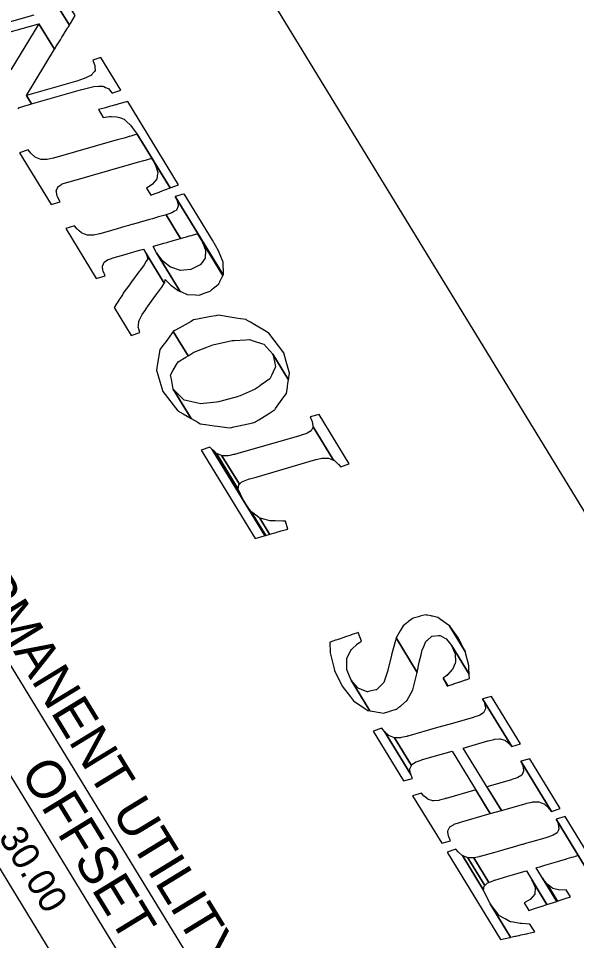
# Model space of a CAD drawing. Extents: x 1753086 to 1770987, y 792577 to 812636.
# Drawn here: x 1766380 to 1767286, y 803112 to 804610 of the extents above; entities that cross this region are included whole.
import ezdxf

# ---------------------------------------------------------------- set-up
doc = ezdxf.new("R2010")
doc.units = 0
for name, color, linetype in [('CTL Sheet Border CELL', 7, 'Continuous'), ('CTL Sheet Notes CELL', 7, 'Continuous'), ('CTL Sheet Table Cell', 7, 'Continuous'), ('CTL Sheet Text', 7, 'Continuous'), ('Sheet Data Field CELL', 7, 'Continuous')]:
    doc.layers.add(name, color=color, linetype=linetype)

msp = doc.modelspace()

# ---------------------------------------------------------------- linework, layer by layer
at = {"layer": 'CTL Sheet Border CELL'}
msp.add_lwpolyline([(1770671.7, 798289.4), (1762511, 811645.8), (1753161.6, 805933.4), (1761322.3, 792577)], close=True, dxfattribs=at)
at = {"layer": 'CTL Sheet Table Cell'}
for p, q in [((1765751, 804567), (1767551.4, 801620.3)), ((1765671.2, 804518.2), (1767471.6, 801571.5)), ((1765591.4, 804469.4), (1767391.8, 801522.7))]:
    msp.add_line(p, q, dxfattribs=at)
at = {"layer": 'Sheet Data Field CELL'}
for points in [[(1766432.4, 804650.2), (1766433.4, 804647.6), (1766462.8, 804599.6), (1766463.1, 804600.1), (1766463.4, 804600.6), (1766463.7, 804601.1), (1766463.7, 804601.2), (1766464.4, 804602.3), (1766472.2, 804615.1), (1766444.4, 804660.6), (1766431.4, 804656.4), (1766430.2, 804656), (1766430.4, 804655.7), (1766431.3, 804653.1)], [(1766472.7, 804507.8), (1766393.1, 804484.9), (1766401.4, 804471.3), (1766480.9, 804494.3), (1766483.2, 804494.9), (1766495.8, 804498), (1766500.2, 804499.1), (1766502.5, 804499.7), (1766509.9, 804500), (1766510.1, 804500), (1766517.3, 804500.3), (1766518.8, 804499.6), (1766521.4, 804498.3), (1766526, 804496.2), (1766526.8, 804495.8), (1766529.7, 804492.2), (1766529.6, 804492.2), (1766532.2, 804489), (1766532.2, 804489.1), (1766533.4, 804489.4), (1766533.4, 804489.5), (1766546.5, 804493.5), (1766513.8, 804547.1), (1766501.1, 804542.4), (1766503.1, 804536.8), (1766503.2, 804536.5), (1766504, 804534.1), (1766504.1, 804532.9), (1766504.2, 804531.8), (1766504.7, 804525.6), (1766503.6, 804524.3), (1766503.1, 804523.6), (1766498.8, 804518.4), (1766498.8, 804518.3), (1766492.9, 804515.4), (1766490.8, 804514.4), (1766487, 804512.6), (1766475, 804508.4)], [(1766519.3, 804464.7), (1766510.1, 804462.1), (1766517.8, 804449.4), (1766527.9, 804450.7), (1766530.5, 804450.7), (1766540.1, 804450.4), (1766544.1, 804449.1), (1766544.1, 804449.1), (1766551.9, 804446.4), (1766555.2, 804443.4), (1766562.3, 804436.8), (1766565, 804433.1), (1766573.1, 804422.1), (1766626.4, 804334.9), (1766640.2, 804340.1), (1766557.6, 804475.3), (1766543, 804471.3), (1766541.9, 804470.9), (1766541.5, 804470.8), (1766538.9, 804470.1), (1766537.7, 804469.7), (1766532.3, 804468.3), (1766529.6, 804467.5), (1766521.6, 804465.3)], [(1766396, 804396.6), (1766381.8, 804391.8), (1766433, 804308.1), (1766447.6, 804312.2), (1766443.5, 804320.6), (1766443, 804321.7), (1766441.8, 804328.6), (1766441.5, 804330.3), (1766443.9, 804336.2), (1766444, 804336.6), (1766450.7, 804340.9), (1766451.3, 804341.3), (1766460.4, 804344.4), (1766460.9, 804344.5), (1766564, 804373.9), (1766573.2, 804376.5), (1766575.4, 804377.1), (1766583.5, 804379.4), (1766586.2, 804380.2), (1766591.5, 804381.7), (1766592.7, 804382), (1766595.3, 804382.8), (1766595.7, 804382.9), (1766596.8, 804383.2), (1766626.3, 804334.8), (1766626.4, 804334.8), (1766573.1, 804422.1), (1766573, 804422.1), (1766571.9, 804421.8), (1766571.5, 804421.7), (1766568.9, 804420.9), (1766567.7, 804420.6), (1766562.4, 804419.1), (1766559.7, 804418.3), (1766551.7, 804416), (1766549.4, 804415.4), (1766540.2, 804412.8), (1766437.1, 804383.5), (1766436.6, 804383.4), (1766426.9, 804381.2), (1766426.1, 804381), (1766416.8, 804381.2), (1766416.4, 804381.2), (1766408.4, 804384.4), (1766407.5, 804384.8), (1766400.7, 804390.8), (1766400.4, 804391.1)], [(1766595.7, 804339.6), (1766587.9, 804334.7), (1766595.1, 804323), (1766603.9, 804326.3), (1766606, 804327.1), (1766613.6, 804330), (1766616.2, 804331), (1766616.2, 804331), (1766621.3, 804332.9), (1766622.4, 804333.3), (1766622.4, 804333.4), (1766624.9, 804334.3), (1766625.3, 804334.4), (1766626.3, 804334.8), (1766596.8, 804383.2), (1766602.6, 804371.6), (1766603, 804370.1), (1766606.3, 804359.8), (1766606, 804357.9), (1766604.9, 804349.5), (1766603.1, 804347.3), (1766597.6, 804340.8)], [(1766624.8, 804292.9), (1766619.9, 804291.2), (1766643.4, 804252.7), (1766648.4, 804254.1), (1766653, 804255.4), (1766658.1, 804256.9), (1766658.1, 804256.9), (1766660.9, 804257.7), (1766661.3, 804257.8), (1766667.4, 804259.5), (1766668, 804259.7), (1766670.6, 804260.5), (1766670.6, 804260.5), (1766671, 804260.6), (1766712.3, 804192.9), (1766712.7, 804193.7), (1766634.8, 804321.1), (1766636.9, 804316.3), (1766637.8, 804314.2), (1766638, 804313.7), (1766639.2, 804307), (1766639.5, 804305.1), (1766636.5, 804298.5), (1766636.1, 804298.3), (1766633.6, 804296.9), (1766629.2, 804294.3)], [(1766635.2, 804321.2), (1766634.8, 804321.1), (1766712.7, 804193.7), (1766712.9, 804194), (1766712.6, 804214.4), (1766704.9, 804232.9), (1766695.1, 804250.2), (1766649.4, 804325.1), (1766648.7, 804324.9), (1766645.6, 804324.1)], [(1766471.2, 804273.5), (1766457, 804268.7), (1766506.5, 804187.8), (1766521.1, 804191.8), (1766518.2, 804198.3), (1766517.9, 804199.2), (1766517.3, 804202.2), (1766516.7, 804206.1), (1766516.4, 804207.8), (1766518.1, 804211.6), (1766518.9, 804213.3), (1766519.4, 804214.4), (1766523, 804216.8), (1766525.6, 804218.3), (1766526.2, 804218.7), (1766526.3, 804218.8), (1766535.3, 804221.9), (1766535.7, 804222), (1766541.6, 804223.7), (1766554.8, 804227.5), (1766554.8, 804227.5), (1766563.7, 804230), (1766571, 804232.1), (1766576.6, 804233.7), (1766580.9, 804234.9), (1766583, 804235.5), (1766616.9, 804179.9), (1766617.6, 804180.9), (1766618.6, 804186.2), (1766627.7, 804176.7), (1766639.4, 804168.3), (1766642.9, 804166.7), (1766604.5, 804229.6), (1766598.8, 804239.9), (1766599.5, 804240.2), (1766605.3, 804241.8), (1766605.4, 804241.8), (1766616.3, 804245), (1766621.2, 804246.4), (1766631.1, 804249.2), (1766639.7, 804251.7), (1766643.4, 804252.7), (1766619.9, 804291.2), (1766616.2, 804290.1), (1766607.6, 804287.7), (1766597.7, 804284.8), (1766592.8, 804283.4), (1766581.9, 804280.3), (1766581.8, 804280.3), (1766576, 804278.6), (1766575.3, 804278.4), (1766574.7, 804278.3), (1766572.5, 804277.7), (1766566.9, 804276), (1766564.2, 804275.2), (1766560.6, 804274.2), (1766559.5, 804273.9), (1766557.4, 804273.3), (1766553.1, 804272.1), (1766547.6, 804270.5), (1766540.3, 804268.4), (1766531.4, 804265.9), (1766518.1, 804262.1), (1766512.3, 804260.4), (1766511.8, 804260.3), (1766502.3, 804258.2), (1766502.1, 804258.1), (1766501.4, 804258), (1766497.8, 804258), (1766492.8, 804258), (1766491.6, 804258.1), (1766489.1, 804259.1), (1766483.7, 804261.3), (1766482.7, 804261.7), (1766478.9, 804265.1), (1766476, 804267.7), (1766475.6, 804268)], [(1766671, 804260.6), (1766678.9, 804247), (1766712.1, 804192.6), (1766712.3, 804192.9)], [(1766608.4, 804224.2), (1766604.5, 804229.6), (1766642.9, 804166.7), (1766643.7, 804166.3), (1766645, 804165.8), (1766645, 804165.8), (1766654.2, 804161.7), (1766654.4, 804161.7), (1766667.6, 804161), (1766673.6, 804160.7), (1766683.1, 804164.2), (1766691.3, 804167.3), (1766694.2, 804169.7), (1766694.2, 804169.7), (1766698.1, 804172.9), (1766701.6, 804175.9), (1766705.6, 804179.1), (1766707, 804182.1), (1766707.3, 804182.6), (1766707.2, 804182.6), (1766710.4, 804189.1), (1766710.8, 804189.8), (1766712.1, 804192.5), (1766712.1, 804192.6), (1766678.9, 804247), (1766679, 804246.7), (1766684.1, 804233.5), (1766684, 804232.3), (1766683.4, 804221.6), (1766683.4, 804220.8), (1766681.6, 804218.4), (1766678.3, 804213.9), (1766675.4, 804209.9), (1766670.9, 804207.7), (1766667.6, 804206.1), (1766659.9, 804202.2), (1766648.7, 804201.4), (1766643.2, 804200.9), (1766627.3, 804206), (1766627, 804206.2), (1766614.4, 804215.9)], [(1766544.2, 804154), (1766535.5, 804140.3), (1766563.3, 804094.9), (1766577.1, 804100.1), (1766576, 804103.7), (1766575.9, 804104.2), (1766574.6, 804108.5), (1766574.8, 804110.9), (1766574.9, 804112), (1766575.5, 804117.7), (1766576.3, 804119.4), (1766576.8, 804120.5), (1766576.8, 804120.5), (1766579.1, 804125.1), (1766580.6, 804128.2), (1766580.6, 804128.2), (1766581, 804129), (1766581.1, 804129.1), (1766586.8, 804137.5), (1766587.1, 804138), (1766590.7, 804143.3), (1766599.1, 804154.9), (1766604.8, 804162.8), (1766609.6, 804169.1), (1766613.2, 804173.8), (1766615.7, 804177.9), (1766616.9, 804179.9), (1766587.5, 804228.1), (1766590, 804219.9), (1766587.6, 804215.6), (1766584.5, 804210), (1766579.8, 804203.8), (1766573.9, 804196.2), (1766565.4, 804184.6), (1766561.7, 804179.5), (1766561.4, 804179.1), (1766555.5, 804171.1), (1766555.4, 804170.9), (1766554.9, 804170.3), (1766553, 804167.7), (1766550.4, 804163.7), (1766549.8, 804162.7), (1766548.9, 804161.2), (1766546.8, 804158), (1766546.4, 804157.4), (1766545.5, 804156), (1766544.9, 804155), (1766544.8, 804154.8)], [(1766634.3, 804103.1), (1766631.5, 804101.4), (1766655.5, 804062.1), (1766658.2, 804063.9), (1766664.8, 804068), (1766685.9, 804076.1), (1766688.6, 804077.1), (1766690.6, 804077.8), (1766690.5, 804077.9), (1766696, 804079.9), (1766717.3, 804084.8), (1766725.2, 804086.6), (1766727.3, 804086.8), (1766730.2, 804086.9), (1766749.6, 804088), (1766755.2, 804088.3), (1766763.1, 804085.8), (1766773.1, 804082.6), (1766774.5, 804082.2), (1766774.5, 804082.2), (1766778.8, 804080.8), (1766793.4, 804064.5), (1766818.7, 804023), (1766820.5, 804033.6), (1766814.9, 804052.9), (1766814.9, 804052.9), (1766810.8, 804067.1), (1766786.8, 804098.9), (1766777, 804104.7), (1766764.1, 804112.3), (1766756.9, 804116.6), (1766751.6, 804119.7), (1766749.7, 804120.8), (1766740.8, 804122.3), (1766733.8, 804123.4), (1766727.4, 804124.5), (1766705.1, 804128.1), (1766702.4, 804127.6), (1766700.4, 804127.2), (1766692.3, 804125.7), (1766670.6, 804121.5), (1766664.6, 804120.4), (1766662.8, 804119.4), (1766660.3, 804118), (1766641.1, 804106.9)], [(1766609.7, 804020.5), (1766614.6, 804004.1), (1766639, 803972.6), (1766647.7, 803967.6), (1766660.7, 803960.2), (1766631.6, 804007.8), (1766628.4, 804024.3), (1766627.1, 804030.7), (1766631, 804037.4), (1766637, 804047.9), (1766639.5, 804052), (1766652, 804059.9), (1766655.5, 804062.1), (1766631.5, 804101.4), (1766628.8, 804097.9), (1766619.3, 804085), (1766616.6, 804081.4), (1766609.7, 804072.1), (1766608.1, 804062), (1766607.5, 804058.5), (1766606, 804049.7), (1766604.2, 804038.7)], [(1766649.4, 803989.9), (1766631.6, 804007.8), (1766660.7, 803960.2), (1766671.3, 803954.1), (1766675.4, 803951.7), (1766684, 803950.5), (1766697.8, 803948.5), (1766703.2, 803947.7), (1766722.3, 803944.9), (1766726.5, 803945.8), (1766729.9, 803946.6), (1766738, 803948.3), (1766760.9, 803953.4), (1766763.8, 803954), (1766765.6, 803955.1), (1766770.4, 803958.1), (1766770.4, 803958.2), (1766788, 803969.1), (1766794.5, 803973.1), (1766796.2, 803974.1), (1766797.7, 803976.4), (1766808.5, 803991.6), (1766811.6, 803996), (1766815.1, 804000.8), (1766816.8, 804011.1), (1766817, 804012.7), (1766817.7, 804017.1), (1766818.7, 804023), (1766793.3, 804064.5), (1766795.8, 804053), (1766797.6, 804044.4), (1766797.1, 804043.3), (1766793.6, 804035.9), (1766790.9, 804030), (1766788.4, 804024.6), (1766774.4, 804014.7), (1766772.3, 804013.2), (1766770.8, 804012.1), (1766764.5, 804007.6), (1766745.2, 803999.4), (1766739.9, 803997.1), (1766738, 803996.3), (1766735.4, 803995.2), (1766713, 803989.2), (1766705.2, 803987.1), (1766701.5, 803986.7), (1766697, 803986.3), (1766680.7, 803984.6), (1766676, 803984.1), (1766661.6, 803987.3), (1766652.5, 803989.3)], [(1766858.2, 803948.4), (1766858.5, 803946.7), (1766891.6, 803892.6), (1766892.6, 803892.2), (1766899.3, 803886.2), (1766899.6, 803885.9), (1766903.3, 803881.7), (1766917.3, 803886.5), (1766868.4, 803966.7), (1766853.8, 803962.7), (1766856.6, 803956.2), (1766857, 803955.3)], [(1766717.2, 803899.6), (1766710.6, 803899.6), (1766738.9, 803853.2), (1766743.1, 803857.3), (1766745.6, 803858.3), (1766748.2, 803859.3), (1766748.2, 803859.4), (1766753.7, 803861.5), (1766755.2, 803862), (1766755.1, 803862), (1766765.9, 803865.1), (1766862.9, 803893.5), (1766863.4, 803893.6), (1766872.8, 803895.7), (1766873.9, 803895.9), (1766882.5, 803895.8), (1766882.5, 803895.9), (1766883.7, 803895.8), (1766891.6, 803892.6), (1766858.5, 803946.7), (1766856, 803941.2), (1766855.5, 803940), (1766849.1, 803936.4), (1766848.2, 803935.9), (1766839.4, 803932.9), (1766838.9, 803932.8), (1766741.6, 803904.9), (1766730.8, 803901.8), (1766729.2, 803901.5), (1766723.2, 803900.2), (1766720.4, 803899.5)], [(1766691, 803913.7), (1766676.9, 803908.9), (1766764.6, 803765.4), (1766779.1, 803769.6), (1766780, 803769.8), (1766694.7, 803909.6)], [(1766695.1, 803909.1), (1766694.6, 803909.6), (1766780, 803769.8), (1766780.2, 803769.9), (1766746, 803825.9), (1766740.7, 803837.4), (1766736.9, 803845.5), (1766736.9, 803845.6), (1766701.7, 803903.3), (1766701.5, 803903.4), (1766698.9, 803905.8)], [(1766708.5, 803900.5), (1766701.7, 803903.3), (1766736.9, 803845.6), (1766738, 803852.2), (1766738.5, 803852.8), (1766738.9, 803853.2), (1766710.6, 803899.6), (1766709.6, 803900)], [(1766758.2, 803808.7), (1766746, 803825.9), (1766780.2, 803769.9), (1766781.7, 803770.3)], [(1766760.5, 803807), (1766758.2, 803808.7), (1766781.7, 803770.3), (1766782.7, 803770.6), (1766782.7, 803770.6), (1766787.1, 803771.8), (1766787.8, 803772), (1766771.8, 803798.3), (1766770.2, 803799.5), (1766760.6, 803806.9)], [(1766772.7, 803798), (1766771.8, 803798.3), (1766787.8, 803772), (1766788.4, 803772.2), (1766794, 803773.8), (1766796.7, 803774.6), (1766799.5, 803775.4), (1766805.3, 803777), (1766806.8, 803777.5), (1766817.6, 803780.5), (1766813.8, 803793.6), (1766809.6, 803793.6), (1766796.9, 803793.7), (1766795.1, 803793.7), (1766788.2, 803793.8), (1766784.3, 803794.9), (1766780.6, 803795.9)], [(1767000, 803614.9), (1766993.4, 803603.6), (1767027.6, 803547.6), (1767030.9, 803564.2), (1767033.9, 803576.1), (1767033.9, 803576.1), (1767035.9, 803584.1), (1767037.6, 803587.9), (1767038.3, 803589.6), (1767041.8, 803597.9), (1767043.3, 803599.2), (1767043.5, 803599.4), (1767051.4, 803606.2), (1767051.9, 803606.3), (1767062.1, 803607.3), (1767063.2, 803607.4), (1767063.2, 803607.5), (1767064.6, 803607.6), (1767072.3, 803603.3), (1767073.9, 803602.4), (1767075.4, 803601.5), (1767083.8, 803590.9), (1767112.1, 803544.5), (1767111.6, 803554.5), (1767111.4, 803558.7), (1767105.4, 803581.5), (1767079.9, 803623.1), (1767065.5, 803633.8), (1767061.2, 803637), (1767054.8, 803638.4), (1767052.6, 803638.8), (1767051.5, 803639), (1767050.3, 803639.3), (1767044.5, 803640.5), (1767042.8, 803640.8), (1767041.4, 803641.1), (1767032.1, 803638.7), (1767031.6, 803638.6), (1767021.2, 803635.9), (1767020.9, 803635.8), (1767019.4, 803634.7), (1767013.5, 803630.1), (1767012.3, 803629.2), (1767009.6, 803627.1), (1767004.9, 803623.5)], [(1766893.2, 803550.8), (1766905.6, 803525.4), (1766919.5, 803507.7), (1766924.3, 803501.6), (1766940.8, 803490.2), (1766947.4, 803485.6), (1766950.8, 803485.1), (1766920.3, 803535), (1766913.8, 803550.7), (1766913.2, 803552.2), (1766913.1, 803552.5), (1766913.4, 803570), (1766913.4, 803570.6), (1766915.4, 803574.6), (1766920.5, 803584.6), (1766921.2, 803585.3), (1766929.3, 803592.9), (1766929.8, 803593.3), (1766933.8, 803596), (1766937, 803598.1), (1766931.7, 803612.3), (1766928.9, 803611.4), (1766925.1, 803610.1), (1766920.5, 803608.5), (1766919.9, 803608.3), (1766909.3, 803604.8), (1766908.3, 803604.5), (1766899.1, 803601.3), (1766895.4, 803600.1), (1766895.1, 803600), (1766886, 803596.9), (1766885.9, 803596.9), (1766885.7, 803596.8), (1766885.9, 803591.3), (1766886.1, 803585.9), (1766886.4, 803579.3), (1766892.5, 803553.6)], [(1767082, 803620.3), (1767079.9, 803623.1), (1767105.4, 803581.5), (1767105.1, 803582.5), (1767094.7, 803603.2)], [(1766930.9, 803522.9), (1766920.3, 803535), (1766950.8, 803485.1), (1766954.3, 803484.5), (1766954.6, 803484.4), (1766954.7, 803484.4), (1766967, 803482.3), (1766967.4, 803482.2), (1766972.4, 803481.4), (1766981.8, 803484.2), (1766982.9, 803484.5), (1766993.6, 803487.6), (1766994.3, 803487.8), (1766998, 803490.9), (1767001, 803493.4), (1767010.4, 803501.1), (1767010.7, 803501.3), (1767020.5, 803519.3), (1767020.6, 803519.5), (1767026.7, 803542.9), (1767027.6, 803547.6), (1766993.4, 803603.6), (1766992.2, 803599.3), (1766986.1, 803576), (1766986.1, 803575.8), (1766980.1, 803551.4), (1766980, 803550.9), (1766974.9, 803536.1), (1766973.3, 803531.3), (1766969.9, 803527.8), (1766969.4, 803527.3), (1766961.6, 803519.2), (1766960.6, 803519), (1766950.7, 803516.8), (1766946.8, 803515.9), (1766946.5, 803515.8), (1766931.9, 803521.7), (1766931.8, 803521.7)], [(1767075.5, 803542.8), (1767069.5, 803538.4), (1767077.4, 803525.6), (1767084.5, 803528), (1767086.4, 803528.7), (1767086.7, 803528.8), (1767096.7, 803532.2), (1767096.6, 803532.2), (1767097.1, 803532.3), (1767106, 803535.4), (1767107, 803535.7), (1767107, 803535.7), (1767108.2, 803536.2), (1767112.4, 803537.6), (1767112.3, 803539.5), (1767112.2, 803541.2), (1767112.1, 803544.5), (1767083.8, 803590.9), (1767087.2, 803582.1), (1767089.1, 803577.6), (1767089.2, 803575.6), (1767089.7, 803566.5), (1767089.8, 803563.9), (1767089.3, 803562.7), (1767084.8, 803552.4), (1767084.5, 803552.1), (1767077.3, 803544.1), (1767077, 803543.9)], [(1767069.5, 803538.4), (1767076, 803525.1), (1767077.4, 803525.6)], [(1767148.4, 803508.5), (1767133.8, 803504.4), (1767181, 803427.1), (1767195.5, 803431.3)], [(1766991.9, 803441.4), (1766990.6, 803441.4), (1767018.1, 803396.3), (1767018.7, 803397.5), (1767018.8, 803397.7), (1767024.6, 803401.5), (1767024.6, 803401.6), (1767025.5, 803402.1), (1767025.8, 803402.2), (1767034.2, 803405.2), (1767034.7, 803405.4), (1767036, 803405.8), (1767084.1, 803419.5), (1767146.1, 803318), (1767164.4, 803323.3), (1767102.4, 803424.7), (1767142.4, 803436.1), (1767142.9, 803436.3), (1767152, 803438.7), (1767153.1, 803439), (1767161.3, 803439.4), (1767161.3, 803439.5), (1767162.5, 803439.5), (1767169.8, 803437.2), (1767170.8, 803436.9), (1767176.8, 803431.9), (1767177.1, 803431.7), (1767181, 803427.1), (1767133.7, 803504.5), (1767136.6, 803498), (1767137, 803497.1), (1767138.2, 803490.2), (1767138.5, 803488.5), (1767135.9, 803482.9), (1767135.4, 803481.8), (1767129.1, 803478.2), (1767128.2, 803477.7), (1767119.4, 803474.7), (1767118.9, 803474.5), (1767079, 803463.1), (1767060.7, 803457.9), (1767012.5, 803444.1), (1767011.3, 803443.8), (1767010.8, 803443.6), (1767001.7, 803441.6), (1767001.4, 803441.6), (1767000.3, 803441.3), (1767000.2, 803441.3), (1766992.1, 803441.4)], [(1766970.1, 803456.9), (1766956, 803452.1), (1767005.5, 803371.1), (1767020.1, 803375.2), (1767017.2, 803381.7), (1766974.6, 803451.3)], [(1766975, 803451.1), (1766974.6, 803451.4), (1767017.2, 803381.7), (1767016.8, 803382.5), (1767015.6, 803389.4), (1767015.4, 803391.1), (1767018.1, 803396.3), (1766990.5, 803441.4), (1766982.6, 803444.7), (1766981.6, 803445.1)], [(1767180.9, 803373.1), (1767140.9, 803361.7), (1767164.4, 803323.3), (1767204.3, 803334.7), (1767204.8, 803334.9), (1767214.2, 803336.9), (1767215.3, 803337.2), (1767223.9, 803337.1), (1767223.8, 803337.1), (1767225.1, 803337.1), (1767233, 803333.8), (1767234, 803333.4), (1767240.7, 803327.4), (1767241, 803327.1), (1767245.5, 803321.6), (1767195.6, 803403.2), (1767198.5, 803396.7), (1767198.9, 803395.8), (1767200.1, 803388.9), (1767200.4, 803387.2), (1767197.8, 803381.6), (1767197.3, 803380.5), (1767191, 803376.9), (1767190.1, 803376.4), (1767181.3, 803373.3)], [(1767210.2, 803407.2), (1767195.7, 803403.2), (1767245.5, 803321.6), (1767259.6, 803326.4)], [(1767034.7, 803351.3), (1767020.2, 803347.1), (1767067.3, 803270), (1767081.9, 803274), (1767079, 803280.5), (1767078.6, 803281.4), (1767077.4, 803288.3), (1767077.2, 803290), (1767079.9, 803295.3), (1767080.5, 803296.5), (1767080.6, 803296.6), (1767086.6, 803300.1), (1767086.6, 803300.1), (1767087.5, 803300.7), (1767087.8, 803300.8), (1767096.3, 803303.6), (1767096.8, 803303.8), (1767098, 803304.2), (1767146.1, 803318), (1767122.6, 803356.5), (1767074.5, 803342.7), (1767073.2, 803342.4), (1767072.7, 803342.2), (1767063.9, 803339.8), (1767063.6, 803339.8), (1767062.6, 803339.5), (1767062.5, 803339.4), (1767054.7, 803339), (1767054.5, 803338.9), (1767053.2, 803338.9), (1767045.8, 803341.2), (1767044.9, 803341.5), (1767038.9, 803346.4), (1767038.6, 803346.7)], [(1767267.6, 803313.3), (1767253, 803309.3), (1767332.4, 803179.3), (1767346.6, 803184.1)], [(1767090.2, 803260.3), (1767076.1, 803255.5), (1767162.9, 803113.5), (1767177.9, 803116.8), (1767178.9, 803117), (1767179.1, 803117.1), (1767145.9, 803171.3), (1767135.3, 803193.5), (1767135.3, 803193.6), (1767100.9, 803249.9), (1767100.7, 803250), (1767094.4, 803255.7), (1767093.9, 803256.2)], [(1767101.4, 803249.7), (1767100.9, 803249.9), (1767135.3, 803193.6), (1767135.4, 803194.1), (1767136.3, 803200.3), (1767137.3, 803201.3), (1767109.8, 803246.2), (1767107.7, 803247.1)], [(1767115.2, 803246.2), (1767109.8, 803246.2), (1767137.3, 803201.3), (1767140.6, 803204.5), (1767141.4, 803205.3), (1767143.9, 803206.3), (1767119.6, 803246.1), (1767116.5, 803246.1)], [(1767211.1, 803178.7), (1767201.4, 803173), (1767208.9, 803160.7), (1767219.9, 803164.3), (1767230.5, 803167.7), (1767236.4, 803169.6), (1767238.3, 803170.3), (1767213.7, 803210.6), (1767219, 803198.1), (1767218.5, 803187.4)], [(1767238.5, 803203.4), (1767230.9, 803213.3), (1767254.1, 803175.4), (1767255.3, 803175.8)], [(1767247.9, 803196.6), (1767238.5, 803203.4), (1767255.3, 803175.8), (1767259.7, 803177.2), (1767267.9, 803179.9), (1767276.6, 803182.7), (1767269.5, 803194.3), (1767259.3, 803193.9)], [(1767159, 803154.7), (1767145.9, 803171.3), (1767179.1, 803117.1), (1767181.6, 803117.6), (1767181.7, 803117.7), (1767182, 803117.7), (1767186.2, 803118.7), (1767187.6, 803119), (1767192.3, 803120), (1767193.4, 803120.2), (1767196.1, 803120.9), (1767205, 803122.9), (1767205.4, 803122.9), (1767206.6, 803123.2), (1767206.5, 803123.2), (1767218.5, 803125.8), (1767210.7, 803138.6), (1767196.7, 803139.4), (1767195.3, 803139.5), (1767194.8, 803139.6), (1767183.5, 803141.5), (1767180, 803142.2), (1767178.6, 803142.4), (1767170.5, 803146.9), (1767168.2, 803148.1), (1767161, 803152.1), (1767159.3, 803154.3)]]:
    msp.add_lwpolyline(points, close=True, dxfattribs=at)
for points in [[(1766335.1, 804579.9), (1766413.5, 804601.7), (1766438.8, 804560.2), (1766439.8, 804561.7), (1766441.1, 804563.9), (1766448.3, 804575.8), (1766450.8, 804579.9), (1766452.1, 804582.1), (1766452.1, 804582.1), (1766455.9, 804588.3), (1766456, 804588.5), (1766459.7, 804594.5), (1766460.2, 804595.4), (1766461.2, 804596.9), (1766462.8, 804599.6), (1766433.4, 804647.7)], [(1766405.1, 804615.4), (1766326.8, 804593.3)], [(1766379.8, 804463.4), (1766381.2, 804465.5), (1766381.8, 804465.7), (1766394.3, 804469.3), (1766400.4, 804471.1), (1766401.4, 804471.3), (1766393.1, 804484.9), (1766438.8, 804560.2), (1766413.5, 804601.7), (1766367.6, 804526.6)], [(1767332.4, 803179.3), (1767253, 803309.3), (1767256.3, 803301.9), (1767256.5, 803300.2), (1767257.1, 803297.2), (1767257.7, 803293.3), (1767256.2, 803289.9), (1767254.7, 803286.6), (1767248.1, 803282.9), (1767247.4, 803282.5), (1767238.2, 803279.3), (1767236.2, 803278.8), (1767234.8, 803278.4), (1767211.7, 803271.8), (1767203.4, 803269.4), (1767198.9, 803268.1), (1767197.6, 803267.8), (1767181.6, 803263.2), (1767179.6, 803262.6), (1767173.6, 803260.9), (1767162.8, 803257.8), (1767151.5, 803254.6), (1767130, 803248.4), (1767128.9, 803248.2), (1767128.5, 803248.1), (1767119.6, 803246.1), (1767143.9, 803206.3), (1767152, 803209.6), (1767152.4, 803209.7), (1767153.5, 803210), (1767174.9, 803216.3), (1767186.1, 803219.7), (1767196.9, 803222.8), (1767202.8, 803224.6), (1767204.8, 803225.2), (1767238.3, 803170.3), (1767254.1, 803175.4), (1767220.7, 803230), (1767222, 803230.4), (1767226.5, 803231.7), (1767234.7, 803234.2), (1767257.6, 803240.9), (1767259.1, 803241.3), (1767261, 803241.9), (1767270.5, 803244.7), (1767271.3, 803245), (1767278.8, 803247.2), (1767281.8, 803248), (1767281.7, 803248.1), (1767284.8, 803248.9), (1767286.3, 803249.4), (1767287.4, 803249.7)]]:
    msp.add_lwpolyline(points, dxfattribs=at)

# ---------------------------------------------------------------- texts
at = {"layer": 'CTL Sheet Notes CELL'}
for s, height, p in [('-Y- PERMANENT UTILITY EASEMENTS', 62.357, (1766175.4, 803902.2)), ('OFFSET', 62.36, (1766381.8, 803385.1))]:
    msp.add_text(s, height=height, rotation=301.4249, dxfattribs=at).set_placement(p)
at = {"layer": 'CTL Sheet Text'}
msp.add_text('30.00', height=44.54, rotation=301.4249, dxfattribs=at).set_placement((1766346.8, 803280))

doc.saveas('drawing.dxf')
